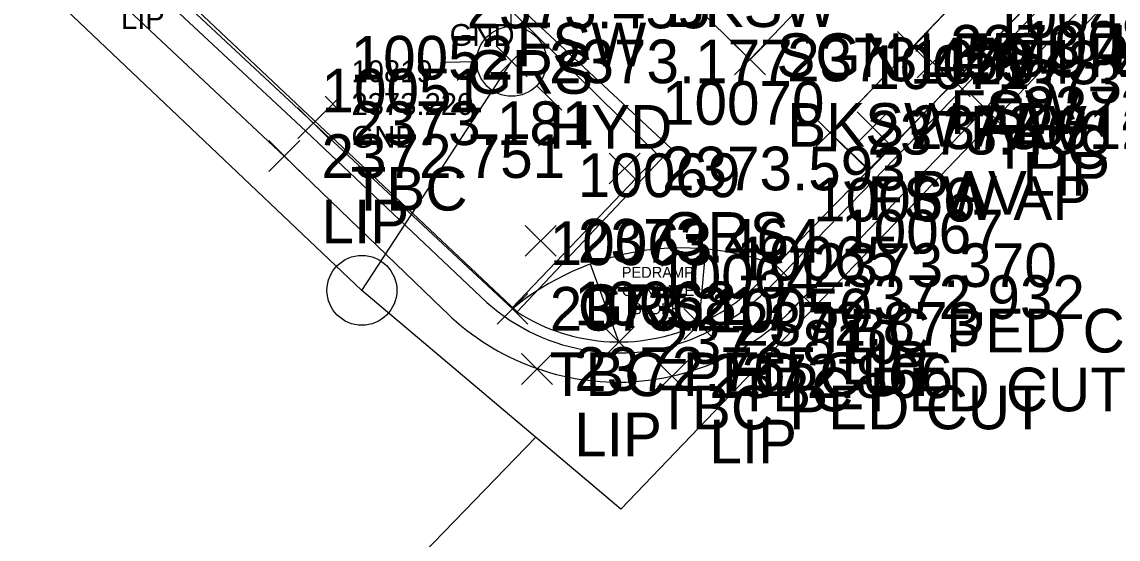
# Model space of a CAD drawing. Extents: x 2377639 to 2379738, y 729875 to 732734.
# Drawn here: x 2378105.9 to 2378156.1, y 730369 to 730392.7 of the extents above; entities that cross this region are included whole.
import ezdxf

# ---------------------------------------------------------------- set-up
doc = ezdxf.new("R2010")
doc.units = 0
for name, color, linetype in [('TOPO_CURBGTR_Back-of-Curb', 7, 'Continuous'), ('TOPO_CURBGTR_Face-of-Curb', 7, 'Continuous'), ('TOPO_CURBGTR_Lip-of-Gutter', 7, 'Continuous'), ('TOPO_DATA_Elevations', 7, 'Continuous'), ('TOPO_DATA_Notes', 7, 'Continuous'), ('TOPO_LNDSCP_Misc', 7, 'Continuous'), ('TOPO_MISC_Flat-Asphalt', 7, 'Continuous'), ('TOPO_SW_Back', 7, 'Continuous'), ('TOPO_WTRUTIL_Fire-Hydrant', 7, 'Continuous'), ('TOPO_WTRUTIL_Line', 7, 'Continuous'), ('TOPO_WTRUTIL_Valve', 7, 'Continuous')]:
    doc.layers.add(name, color=color, linetype=linetype)

msp = doc.modelspace()

# ---------------------------------------------------------------- linework, layer by layer
at = {"layer": 'TOPO_CURBGTR_Back-of-Curb'}
msp.add_line((2378119.279, 730388.079), (2378128.392, 730379.579), dxfattribs=at)
for points in [[(2378139.753, 730380.865), (2378148.64, 730389.997), (2378225.837, 730470.65), (2378251.518, 730497.426), (2378309.295, 730557.655), (2378317.456, 730566.28)], [(2378119.279, 730388.079), (2378110.587, 730396.202), (2378090.198, 730415.739)]]:
    msp.add_lwpolyline(points, dxfattribs=at)
for centre, radius, start, end in [((2378132.998, 730387.476), 9.452, 294.6358, 315.6168), ((2378133.267, 730386.649), 8.588, 235.4105, 295.3042)]:
    msp.add_arc(centre, radius, start, end, dxfattribs=at)
at = {"layer": 'TOPO_CURBGTR_Face-of-Curb'}
msp.add_line((2378118.938, 730387.713), (2378127.217, 730379.873), dxfattribs=at)
for points in [[(2378140.262, 730380.667), (2378149, 730389.65), (2378226.198, 730470.304), (2378251.879, 730497.08), (2378309.657, 730557.31), (2378317.819, 730565.936)], [(2378118.938, 730387.713), (2378110.243, 730395.839), (2378089.852, 730415.378)]]:
    msp.add_lwpolyline(points, dxfattribs=at)
for centre, radius, start, end in [((2378132.909, 730387.622), 10.121, 294.7845, 316.5931), ((2378133.269, 730386.637), 9.076, 228.1775, 295.3237)]:
    msp.add_arc(centre, radius, start, end, dxfattribs=at)
at = {"layer": 'TOPO_CURBGTR_Lip-of-Gutter'}
msp.add_line((2378125.197, 730379.581), (2378117.945, 730386.574), dxfattribs=at)
for points in [[(2378319.904, 730566.205), (2378310.745, 730556.446), (2378281.259, 730525.513), (2378150.03, 730388.754), (2378141.734, 730380.114)], [(2378088.895, 730414.34), (2378109.615, 730394.398), (2378117.945, 730386.574)]]:
    msp.add_lwpolyline(points, dxfattribs=at)
msp.add_arc((2378133.219, 730387.476), 11.256, 224.5421, 319.152, dxfattribs=at)
at = {"layer": 'TOPO_DATA_Elevations'}
for p, q in [((2378146.016, 730390.871), (2378147.43, 730392.285)), ((2378146.016, 730392.285), (2378147.43, 730390.871)), ((2378127.649, 730390.204), (2378129.063, 730391.618)), ((2378127.649, 730391.618), (2378129.063, 730390.204)), ((2378138.556, 730390.293), (2378139.97, 730391.707)), ((2378138.556, 730391.707), (2378139.97, 730390.293)), ((2378146.919, 730390.155), (2378148.333, 730391.569)), ((2378146.919, 730391.569), (2378148.333, 730390.155)), ((2378147.933, 730389.29), (2378149.347, 730390.704)), ((2378147.933, 730390.704), (2378149.347, 730389.29)), ((2378119.813, 730388.604), (2378120.521, 730389.312)), ((2378119.813, 730389.312), (2378120.521, 730388.604)), ((2378119.813, 730388.604), (2378120.521, 730389.312)), ((2378119.813, 730389.312), (2378120.521, 730388.604)), ((2378149.323, 730388.047), (2378150.737, 730389.461)), ((2378149.323, 730389.461), (2378150.737, 730388.047)), ((2378118.572, 730387.372), (2378119.986, 730388.786)), ((2378118.572, 730388.786), (2378119.986, 730387.372)), ((2378142.225, 730386.938), (2378143.639, 730388.352)), ((2378142.225, 730388.352), (2378143.639, 730386.938)), ((2378144.178, 730387.187), (2378145.592, 730388.601)), ((2378144.178, 730388.601), (2378145.592, 730387.187)), ((2378117.238, 730385.867), (2378118.652, 730387.281)), ((2378117.238, 730387.281), (2378118.652, 730385.867)), ((2378132.824, 730385.299), (2378134.238, 730386.713)), ((2378132.824, 730386.713), (2378134.238, 730385.299)), ((2378128.972, 730381.988), (2378130.386, 730383.402)), ((2378128.972, 730383.402), (2378130.386, 730381.988)), ((2378139.743, 730380.872), (2378141.157, 730382.286)), ((2378139.743, 730382.286), (2378141.157, 730380.872)), ((2378141.027, 730379.407), (2378142.441, 730380.821)), ((2378141.027, 730380.821), (2378142.441, 730379.407)), ((2378127.685, 730378.872), (2378129.099, 730380.286)), ((2378127.685, 730380.286), (2378129.099, 730378.872)), ((2378136.231, 730378.178), (2378137.645, 730379.592)), ((2378136.231, 730379.592), (2378137.645, 730378.178)), ((2378132.558, 730377.354), (2378133.972, 730378.768)), ((2378132.558, 730378.768), (2378133.972, 730377.354)), ((2378128.808, 730376.115), (2378130.222, 730377.529)), ((2378128.808, 730377.529), (2378130.222, 730376.115)), ((2378134.99, 730375.79), (2378136.404, 730377.204)), ((2378134.99, 730377.204), (2378136.404, 730375.79))]:
    msp.add_line(p, q, dxfattribs=at)
at = {"layer": 'TOPO_LNDSCP_Misc'}
for points in [[(2378110.246, 730396.771), (2378116.19, 730405.07), (2378135.663, 730386.918)], [(2378135.663, 730386.918), (2378128.606, 730379.436), (2378110.246, 730396.771)]]:
    msp.add_lwpolyline(points, dxfattribs=at)
at = {"layer": 'TOPO_MISC_Flat-Asphalt'}
msp.add_lwpolyline([(2378142.932, 730387.645), (2378190.637, 730437.477), (2378192.437, 730435.754), (2378144.732, 730385.922)], close=True, dxfattribs=at)
at = {"layer": 'TOPO_SW_Back'}
for p, q in [((2378136.938, 730378.885), (2378137.25, 730382.314)), ((2378133.265, 730378.061), (2378131.963, 730381.624))]:
    msp.add_line(p, q, dxfattribs=at)
for points in [[(2378133.698, 730396.486), (2378139.263, 730391), (2378146.3, 730398.349), (2378224.625, 730480.085)], [(2378224.032, 730472.38), (2378146.723, 730391.578), (2378142.932, 730387.645), (2378144.689, 730385.936)], [(2378126.872, 730394.689), (2378135.063, 730386.614), (2378128.358, 730379.611)]]:
    msp.add_lwpolyline(points, dxfattribs=at)
msp.add_arc((2378136.146, 730370.178), 12.187, 69.3193, 129.5159, dxfattribs=at)
at = {"layer": 'TOPO_WTRUTIL_Fire-Hydrant'}
for p, q in [((2378128.332, 730392.495), (2378128.309, 730394.078)), ((2378126.772, 730390.887), (2378125.189, 730390.864)), ((2378129.504, 730389.797), (2378130.652, 730388.682))]:
    msp.add_line(p, q, dxfattribs=at)
msp.add_circle((2378128.356, 730390.911), 1.6, dxfattribs=at)
at = {"layer": 'TOPO_WTRUTIL_Line'}
for p, q in [((2378133.356, 730370.41), (2378391.806, 730640.09)), ((2377982.698, 730512.231), (2378121.502, 730380.425)), ((2378121.502, 730380.425), (2378128.356, 730390.911)), ((2378133.356, 730370.41), (2378121.502, 730380.425)), ((2378014.539, 730254.955), (2378129.455, 730373.706))]:
    msp.add_line(p, q, dxfattribs=at)
at = {"layer": 'TOPO_WTRUTIL_Valve'}
msp.add_circle((2378121.502, 730380.425), 1.6, dxfattribs=at)

# ---------------------------------------------------------------- texts
at = {"layer": 'TOPO_DATA_Elevations'}
for s, height, p in [('2373.455', 2, (2378126.292, 730392.427)), ('BKSW', 2, (2378135.405, 730392.486)), ('10048', 2, (2378150.347, 730391.997)), ('LIP', 1, (2378110.469, 730392.398)), ('LIP', 1, (2378110.469, 730392.398)), ('10049', 2, (2378151.737, 730390.754)), ('GND', 1, (2378125.518, 730391.622)), ('GND', 1, (2378125.518, 730391.622)), ('FSW', 2, (2378128.579, 730390.689)), ('2373.403', 2, (2378148.43, 730390.578)), ('10052', 2, (2378120.986, 730390.079)), ('2373.177', 2, (2378130.063, 730389.911)), ('SGN LEISURE VILLAGE', 2, (2378140.475, 730390.195)), ('2373.459', 2, (2378140.97, 730390)), ('10074', 2, (2378146.592, 730389.894)), ('2373.401', 2, (2378149.333, 730389.862)), ('GRS', 2, (2378126.292, 730389.427)), ('10071', 2, (2378144.639, 730389.645)), ('10819', 1, (2378121.021, 730389.958)), ('10819', 1, (2378121.021, 730389.958)), ('2373.381', 2, (2378150.347, 730388.997)), ('10051', 2, (2378119.652, 730388.574)), ('10070', 2, (2378135.238, 730388.006)), ('2372.974', 2, (2378151.737, 730387.754)), ('2373.220', 1, (2378121.021, 730388.458)), ('2373.220', 1, (2378121.021, 730388.458)), ('FSW', 2, (2378148.43, 730387.578)), ('2373.181', 2, (2378120.986, 730387.079)), ('HYD', 2, (2378130.063, 730386.911)), ('BKSW AP', 2, (2378140.97, 730387)), ('2373.612', 2, (2378146.592, 730386.894)), ('PAV', 2, (2378149.333, 730386.862)), ('2373.466', 2, (2378144.639, 730386.645)), ('GND', 1, (2378121.021, 730386.958)), ('GND', 1, (2378121.021, 730386.958)), ('TBC', 2, (2378150.347, 730385.997)), ('2372.751', 2, (2378119.652, 730385.574)), ('10069', 2, (2378131.386, 730384.695)), ('2373.593', 2, (2378135.238, 730385.006)), ('LIP', 2, (2378151.737, 730384.754)), ('TBC', 2, (2378120.986, 730384.079)), ('PAV', 2, (2378146.592, 730383.894)), ('10066', 2, (2378142.157, 730383.579)), ('FSW AP', 2, (2378144.639, 730383.645)), ('LIP', 2, (2378119.652, 730382.574)), ('2373.464', 2, (2378131.386, 730381.695)), ('GRS', 2, (2378135.238, 730382.006)), ('10067', 2, (2378143.441, 730382.114)), ('10063', 2, (2378130.099, 730381.579)), ('10065', 2, (2378138.645, 730380.885)), ('2373.370', 2, (2378142.157, 730380.579)), ('10064', 2, (2378134.972, 730380.061)), ('10068', 2, (2378131.222, 730378.822)), ('GRS', 2, (2378131.386, 730378.695)), ('2372.932', 2, (2378143.441, 730379.114)), ('2373.217', 2, (2378130.099, 730378.579)), ('10050', 2, (2378137.404, 730378.497)), ('2372.873', 2, (2378138.645, 730377.885)), ('TBC PED CUT', 2, (2378142.157, 730377.579)), ('2372.810', 2, (2378134.972, 730377.061)), ('2372.765', 2, (2378131.222, 730375.822)), ('LIP', 2, (2378143.441, 730376.114)), ('TBC PED CUT', 2, (2378130.099, 730375.579)), ('2372.866', 2, (2378137.404, 730375.497)), ('TBC PED CUT', 2, (2378138.645, 730374.885)), ('TBC PED CUT', 2, (2378134.972, 730374.061)), ('LIP', 2, (2378131.222, 730372.822)), ('LIP', 2, (2378137.404, 730372.497))]:
    msp.add_text(s, height=height, dxfattribs=at).set_placement(p)
at = {"layer": 'TOPO_DATA_Notes'}
for s, p in [('PEDRAMP ', (2378133.393, 730381)), ('CONCAVE ', (2378133.403, 730380.166)), ('SLOPE ', (2378133.86, 730379.333))]:
    msp.add_text(s, height=0.5, dxfattribs=at).set_placement(p)

doc.saveas('drawing.dxf')
